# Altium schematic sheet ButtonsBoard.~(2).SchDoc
size A4
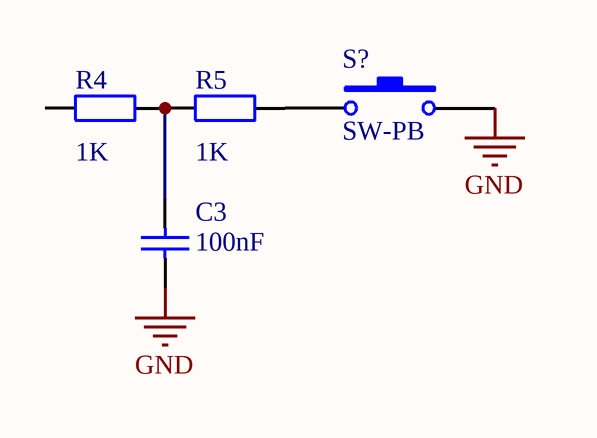
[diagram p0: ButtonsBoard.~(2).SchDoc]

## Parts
C3  value 100nF  [RAD-0.3]  (hidden comment: Cap)
R4  value 1K  [AXIAL-0.4]  (hidden comment: Res2)
R5  value 1K  [AXIAL-0.4]  (hidden comment: Res2)
S?  SW-PB  [SPST-2]

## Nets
GND: C3.1 S?.2
NetC3_2: C3.2 R4.2 R5.1
NetR5_2: R5.2 S?.1

Not connected (* = marked no-connect by the designer): R4 1

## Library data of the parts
C3 = Cap: Capacitor
R4 R5 = Res2: Resistor
S? = SW-PB: Switch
